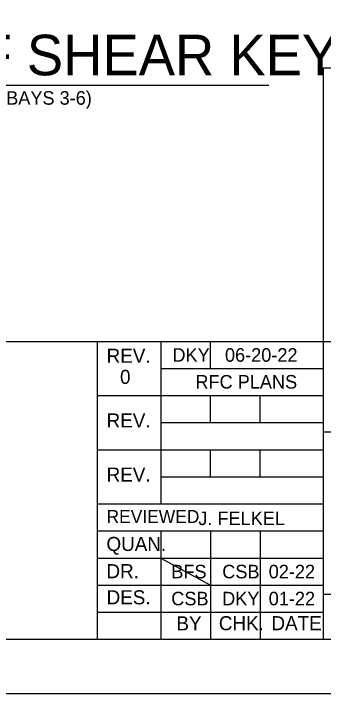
# Model space of a CAD drawing. Extents: x -146.3 to -98.2, y -113.4 to -84.1.
# Drawn here: x -110.01 to -106.2, y -113.39 to -105.02 of the extents above; entities that cross this region are included whole.
import ezdxf

# ---------------------------------------------------------------- set-up
doc = ezdxf.new("R2010")
doc.units = 0
for name, color, linetype in [('BR_AUTO DIMENSION', 7, 'Continuous'), ('BR_BORDER LINES', 7, 'Continuous'), ('BR_TEXT', 7, 'Continuous'), ('Level 31', 7, 'Continuous')]:
    doc.layers.add(name, color=color, linetype=linetype)

msp = doc.modelspace()

# ---------------------------------------------------------------- linework, layer by layer
at = {"layer": 'BR_BORDER LINES'}
for p, q in [((-106.201, -112.7249), (-106.201, -105.6896)), ((-106.201, -105.6896), (-98.9787, -105.6896)), ((-116.1323, -109.0582), (-108.9789, -109.0582)), ((-108.9789, -112.7249), (-108.9789, -109.0582)), ((-108.9789, -109.0582), (-98.9787, -109.0582)), ((-108.2011, -109.0582), (-108.2011, -111.0582)), ((-107.59, -109.3915), (-107.59, -109.0582)), ((-108.2011, -109.3915), (-106.201, -109.3915)), ((-108.9789, -109.7248), (-106.201, -109.7248)), ((-107.59, -110.0582), (-107.59, -109.7248)), ((-106.9788, -110.0582), (-106.9788, -109.7248)), ((-108.2011, -110.0582), (-106.201, -110.0582)), ((-106.201, -110.1693), (-106.201, -110.1693)), ((-106.201, -110.1693), (-98.9784, -110.1693)), ((-108.9789, -110.3915), (-106.201, -110.3915)), ((-107.59, -110.7248), (-107.59, -110.3915)), ((-106.9788, -110.7248), (-106.9788, -110.3915)), ((-108.2011, -110.7248), (-106.201, -110.7248)), ((-108.9789, -111.0582), (-106.201, -111.0582)), ((-108.9789, -111.3915), (-106.201, -111.3915)), ((-108.2011, -111.3915), (-108.2011, -112.7249)), ((-107.59, -111.3915), (-107.59, -112.7249)), ((-106.9788, -111.3915), (-106.9788, -112.7249)), ((-108.9789, -111.7249), (-106.201, -111.7249)), ((-108.9789, -112.0582), (-106.201, -112.0582)), ((-106.201, -112.1693), (-98.9787, -112.1693)), ((-108.9789, -112.3915), (-106.201, -112.3915)), ((-143.8657, -112.7249), (-98.9787, -112.7249))]:
    msp.add_line(p, q, dxfattribs=at)
at = {"layer": 'BR_TEXT'}
msp.add_line((-112.8932, -105.9013), (-106.8727, -105.9013), dxfattribs=at)
at = {"layer": 'Level 31'}
msp.add_line((-108.2011, -111.7249), (-107.59, -112.0582), dxfattribs=at)
msp.add_lwpolyline([(-146.31, -113.3914), (-98.3112, -113.3914), (-98.3112, -84.0588), (-146.31, -84.0588)], close=True, dxfattribs=at)

# ---------------------------------------------------------------- texts
at = {"layer": 'BR_AUTO DIMENSION'}
msp.add_text('(BENT 4 BAYS 3-6)', height=0.166662, dxfattribs=at).set_placement((-111.0167, -106.144))
at = {"layer": 'BR_TEXT'}
msp.add_text('PLAN OF SHEAR KEY', height=0.500062, rotation=0.00001, dxfattribs=at).set_placement((-112.8932, -105.7822))
for s, height, p in [('REV.', 0.17334, (-108.8659, -109.3209)), ('DKY', 0.16666, (-108.0566, -109.3082)), ('06-20-22', 0.16666, (-107.4107, -109.3082)), ('0', 0.1733, (-108.7008, -109.5809)), ('RFC PLANS', 0.16666, (-107.7744, -109.6383)), ('REV.', 0.17334, (-108.8659, -110.1176)), ('REV.', 0.17334, (-108.8659, -110.7843)), ('REVIEWED', 0.16, (-108.8668, -111.2935)), ('J. FELKEL', 0.16666, (-107.7383, -111.319)), ('QUAN.', 0.17334, (-108.8677, -111.638)), ('DR.', 0.17334, (-108.8674, -111.9733)), ('BFS', 0.16666, (-108.0708, -111.9749)), ('CSB', 0.16666, (-107.4443, -111.9749)), ('02-22', 0.16666, (-106.8731, -111.9749)), ('DES.', 0.17334, (-108.866, -112.2951)), ('CSB', 0.16666, (-108.0708, -112.307)), ('DKY', 0.16666, (-107.4453, -112.307)), ('01-22', 0.16666, (-106.8731, -112.307)), ('BY', 0.17334, (-108.0073, -112.6156)), ('CHK.', 0.17334, (-107.4862, -112.6138)), ('DATE', 0.17334, (-106.8393, -112.6136))]:
    msp.add_text(s, height=height, dxfattribs=at).set_placement(p)

doc.saveas('drawing.dxf')
